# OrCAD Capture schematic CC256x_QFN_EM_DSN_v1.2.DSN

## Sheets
1 Page1 - Board Interafce: size B; title: CC256xQFN-EM; rev: 1.2
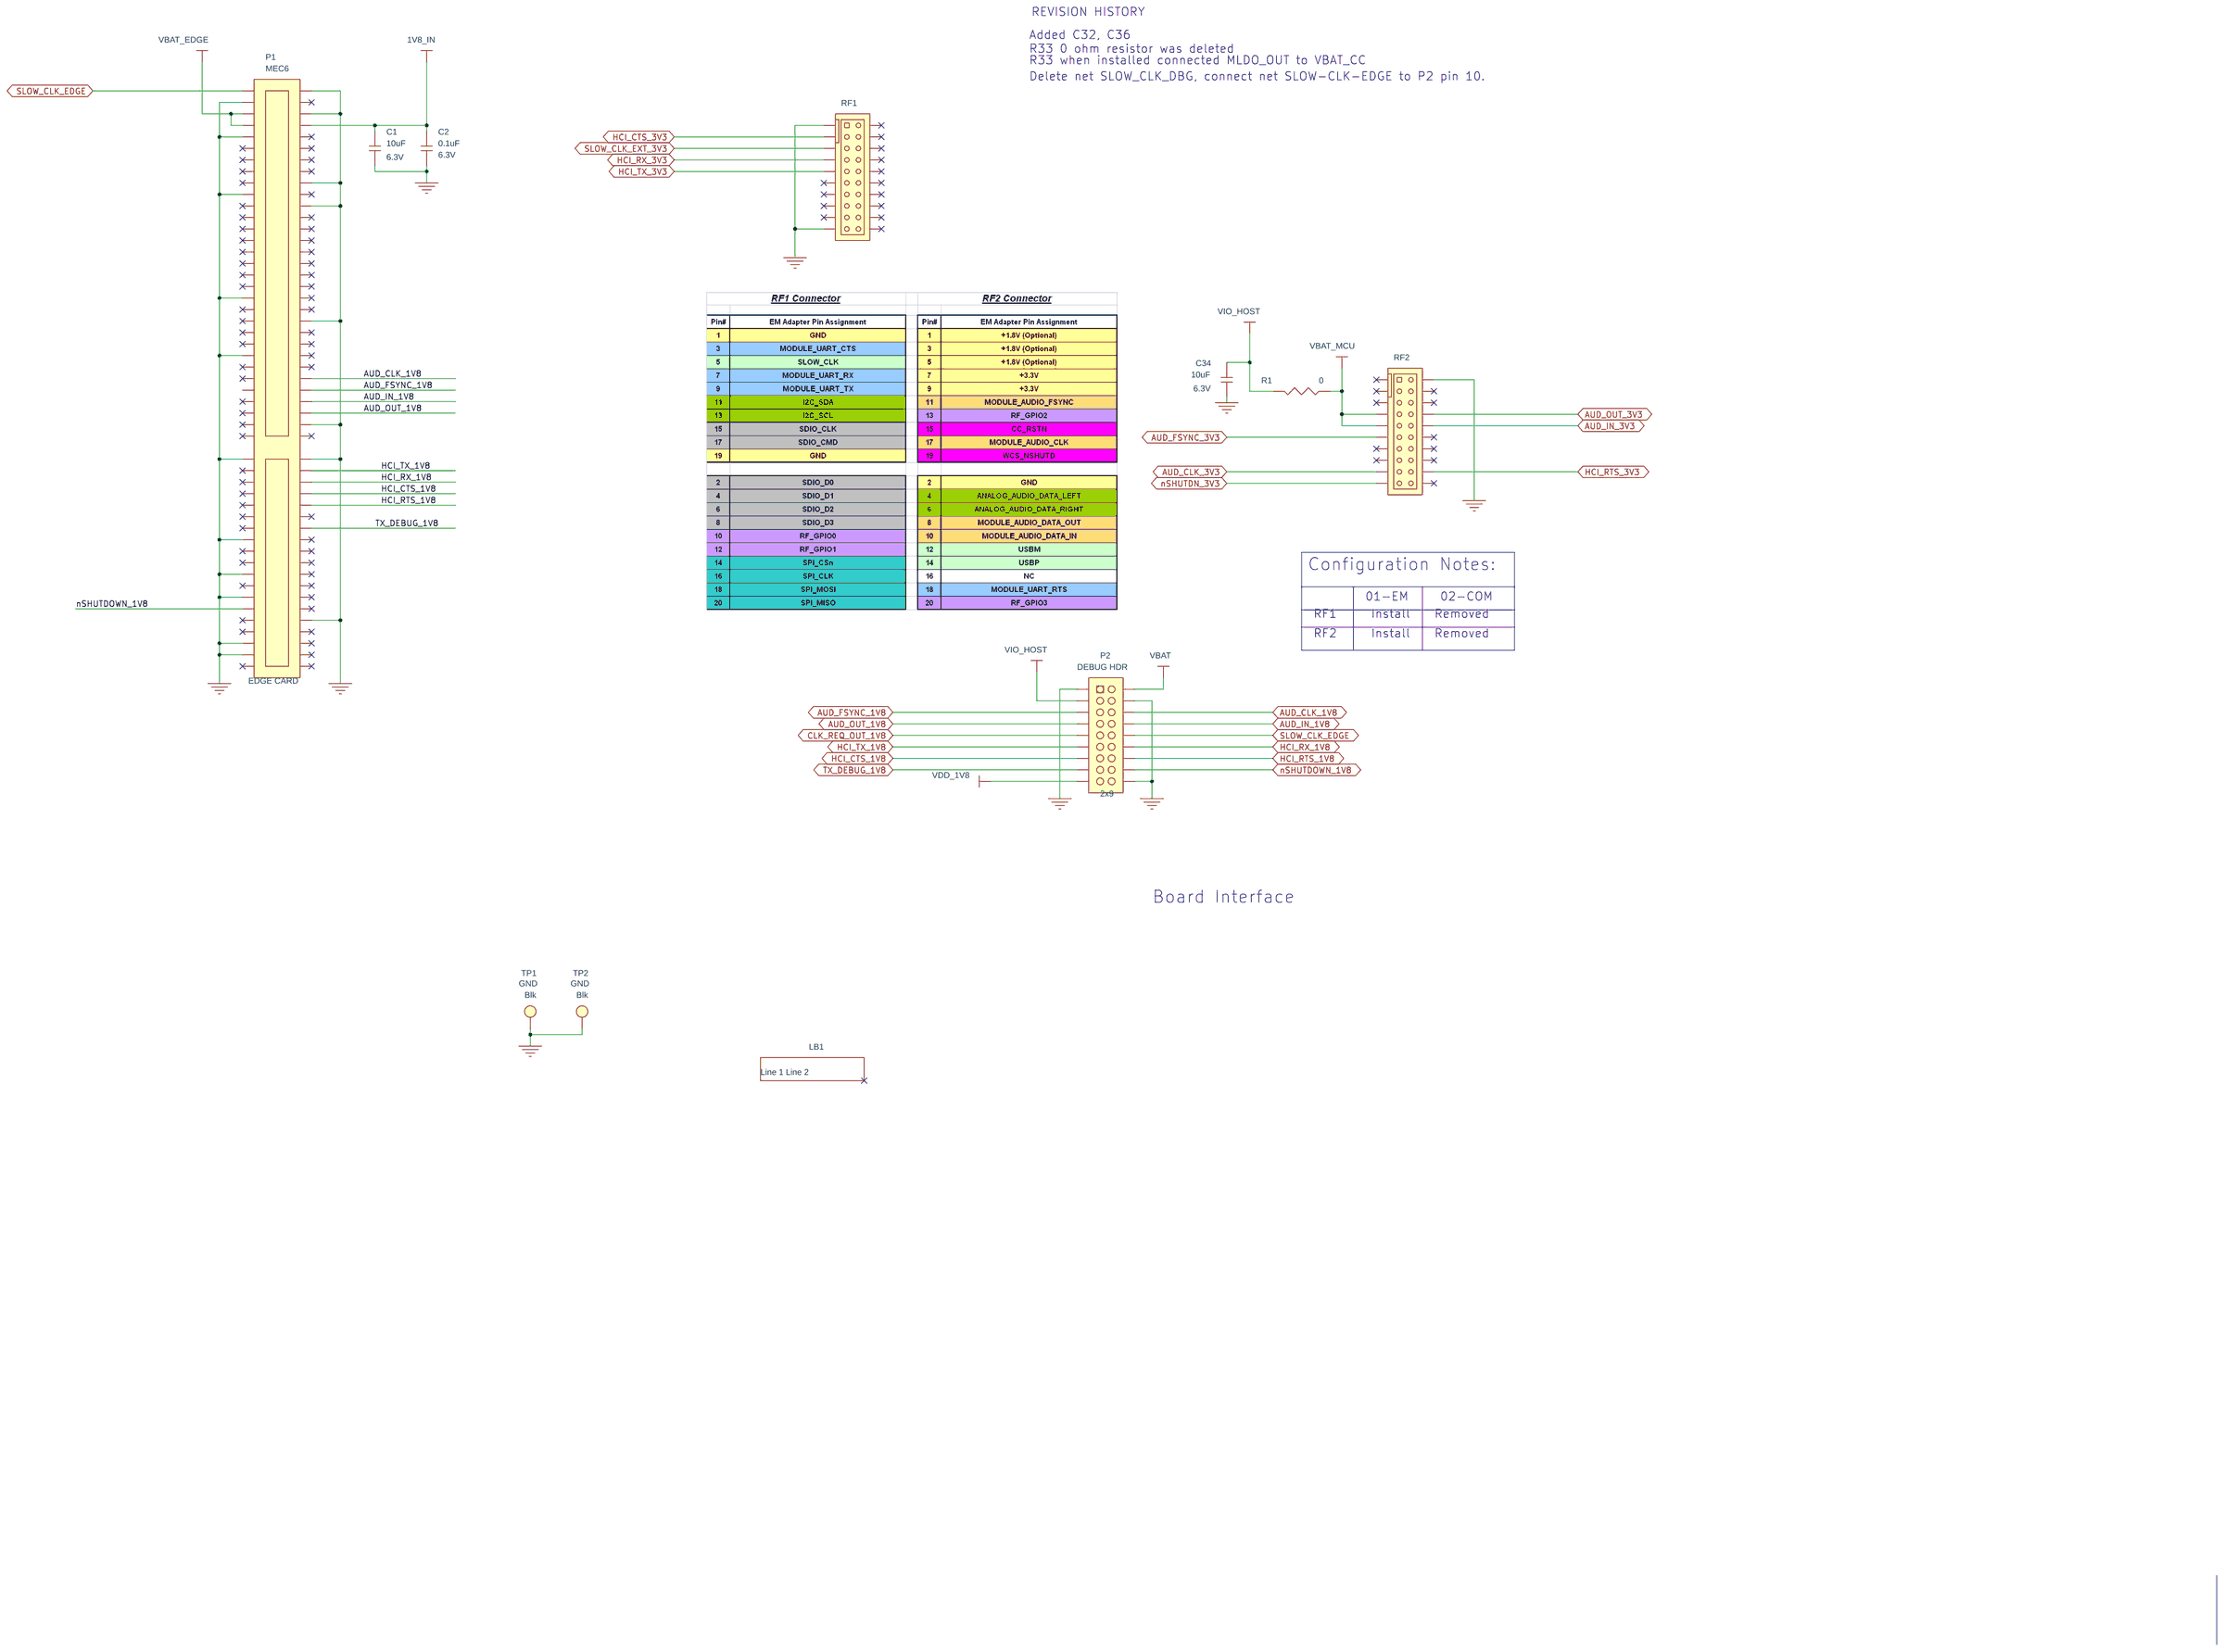
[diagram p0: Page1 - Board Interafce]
2 Page2 - POWER: size B
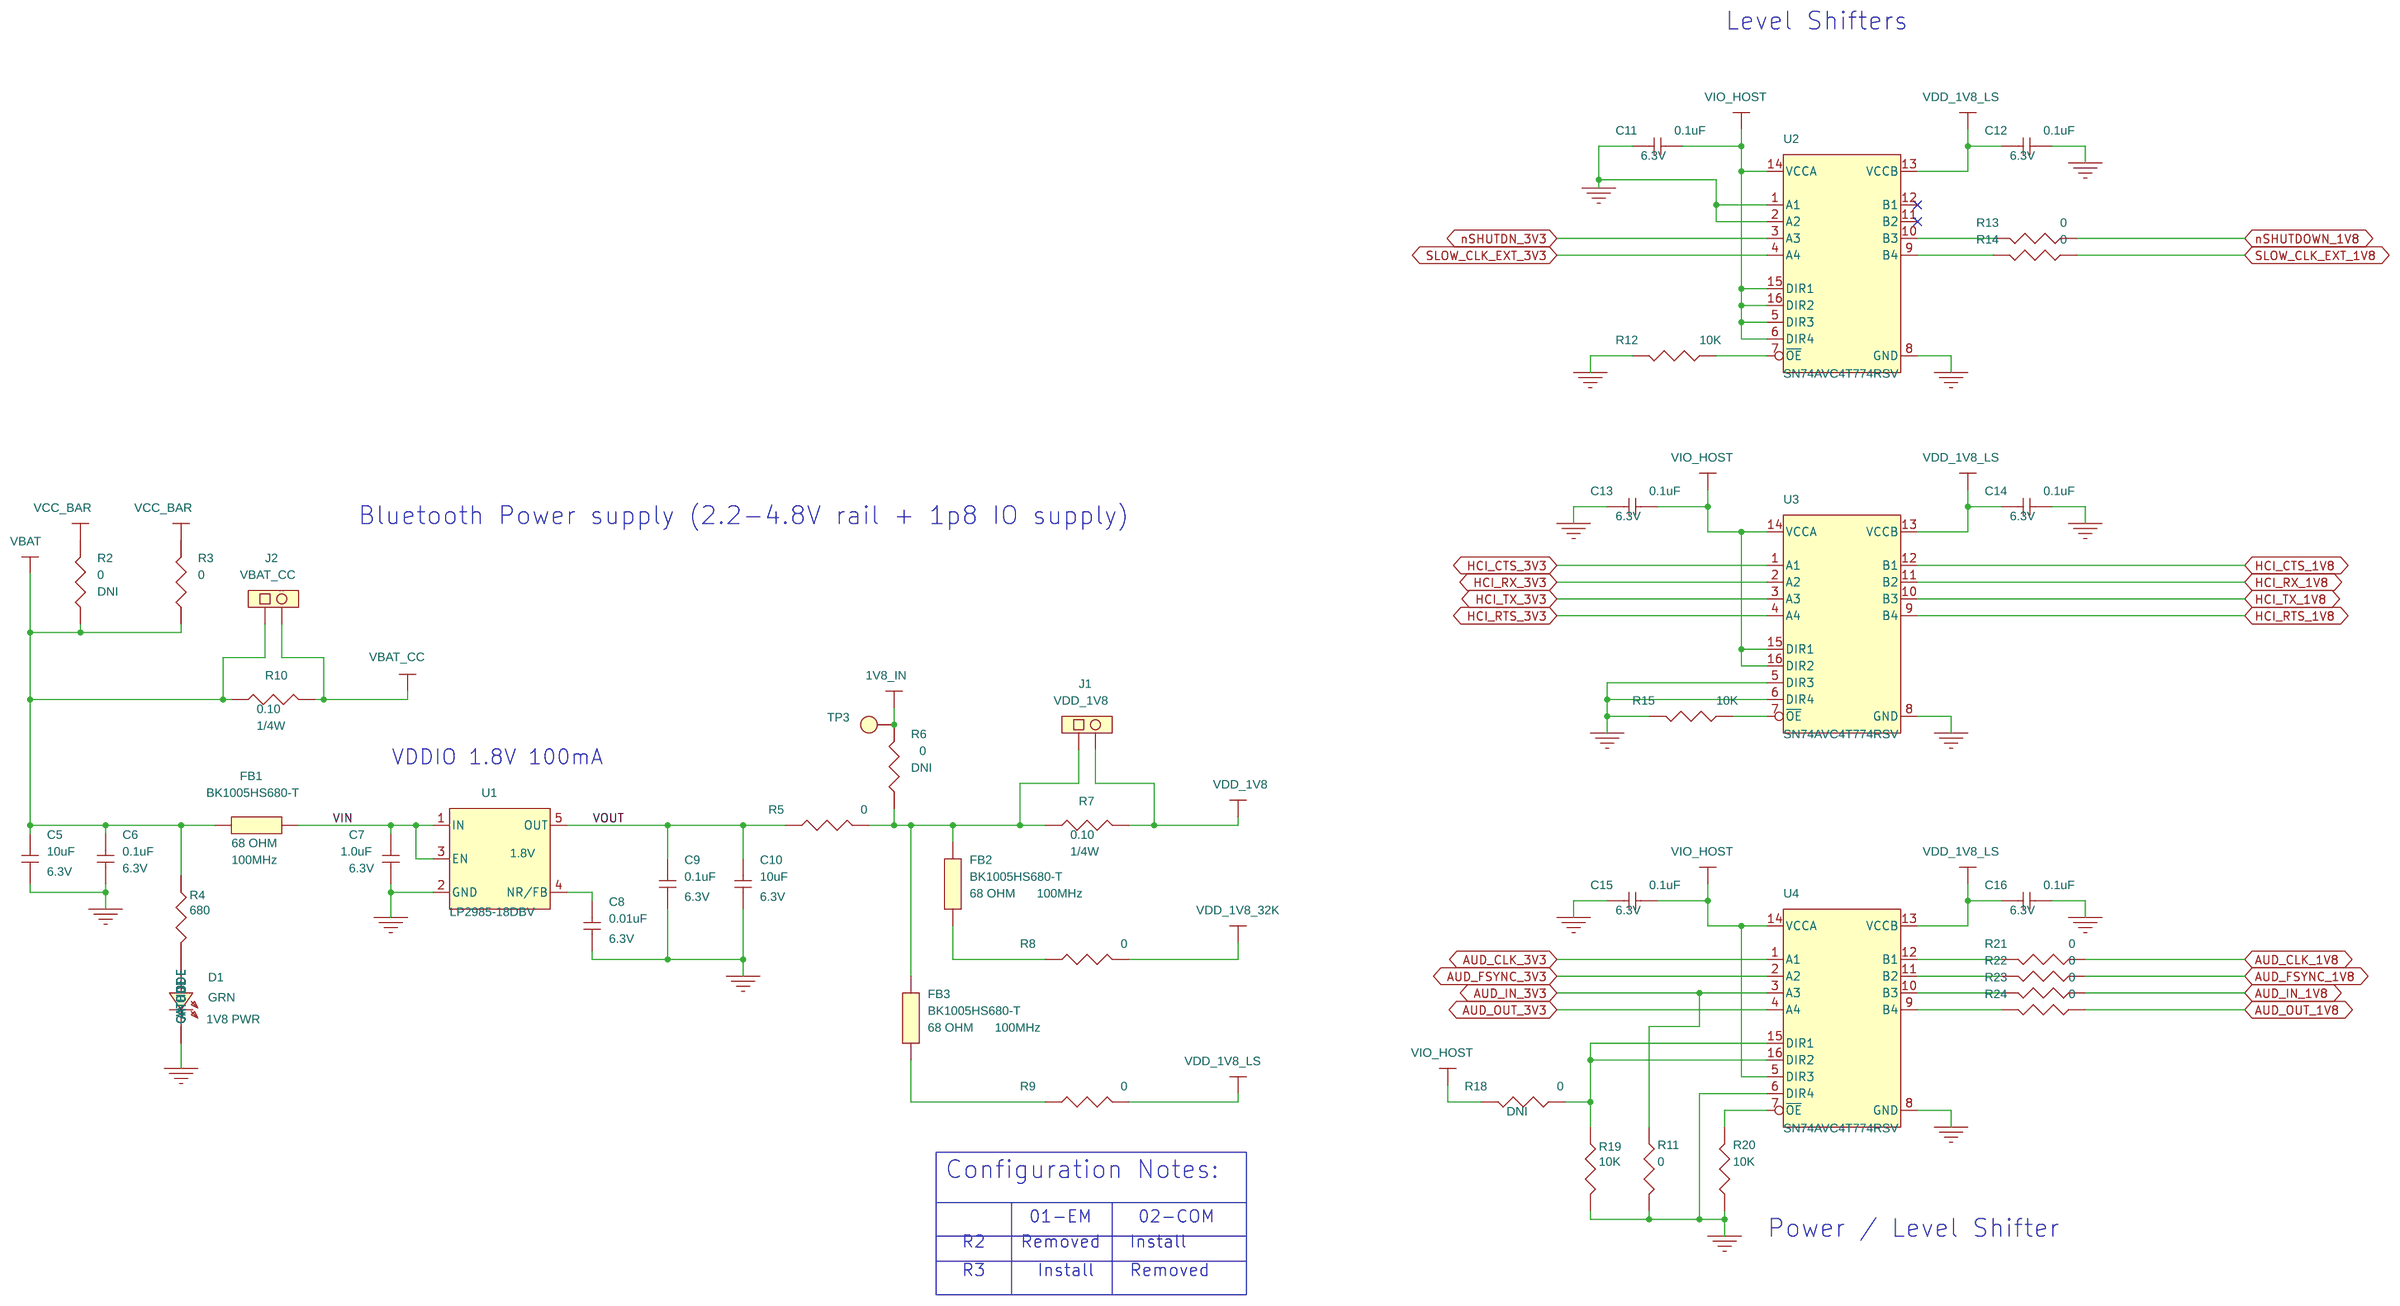
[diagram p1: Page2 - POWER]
3 Page3 - CC256x QFN: size B
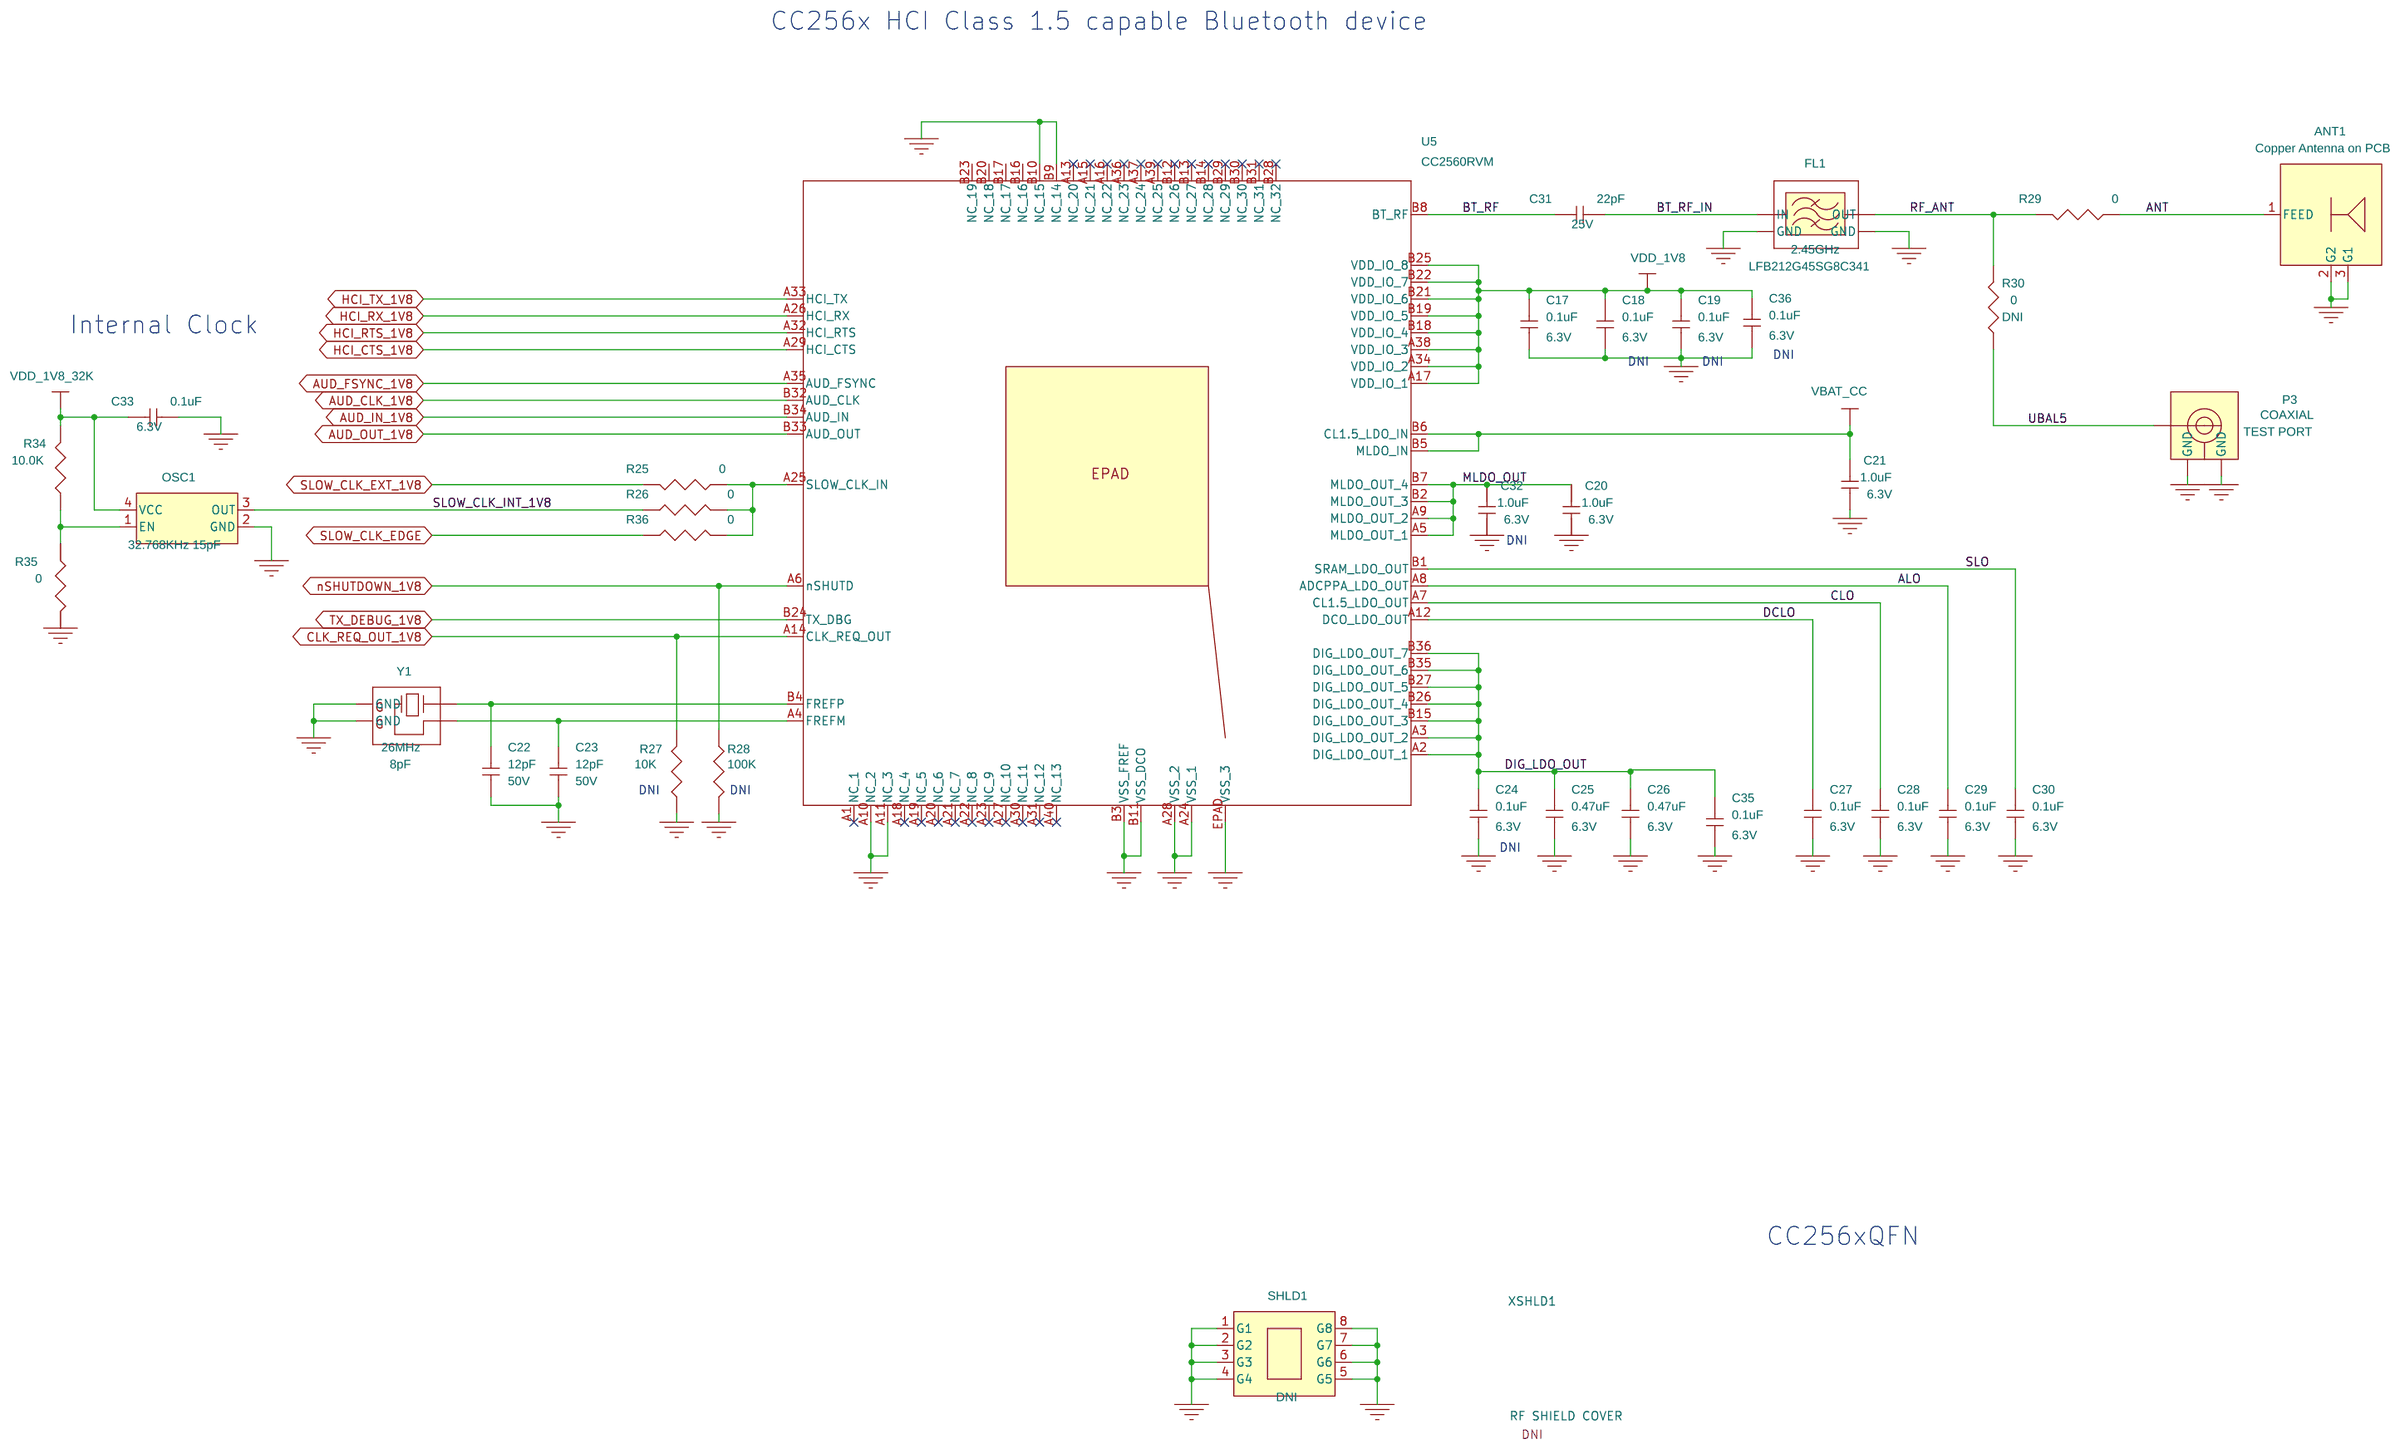
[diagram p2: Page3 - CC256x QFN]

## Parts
sheet Page1 - Board Interafce
C1  10uF  [0603]
C2  0.1uF  [0402]
C34  10uF  [0603]
LB1  Line 1 Line 2  [LABEL_THT-14]
P1  EDGE CARD  [CON_EDGE_50_P635mm]
P2  2x9  [HDR_THVT_2x9_100_M]
R1  0  [0402]
RF1  2x10 SMVT  [CON_SMVT_2x10_50_F_SFM_FLIP_CC]
RF2  2x10 SMVT  [CON_SMVT_2x10_50_F_SFM_FLIP_CC]
TP1  Blk  [TP_THVT_060_RND]
TP2  Blk  [TP_THVT_060_RND]
sheet Page2 - POWER
C5  10uF  [0603]
C6  0.1uF  [0402]
C7  1.0uF  [0402]
C8  0.01uF  [0402]
C9  0.1uF  [0402]
C10  10uF  [0603]
C11  0.1uF  [0402]
C12  0.1uF  [0402]
C13  0.1uF  [0402]
C14  0.1uF  [0402]
C15  0.1uF  [0402]
C16  0.1uF  [0402]
D1  GRN  [LED_0603]
FB1  BK1005HS680-T  [FB_0402]
FB2  BK1005HS680-T  [FB_0402]
FB3  BK1005HS680-T  [FB_0402]
J1  1x2 THVT  [HDR_THVT_1x2_100_M]
J2  1x2 THVT  [HDR_THVT_1x2_100_M]
R2  0  [0402]
R3  0  [0402]
R4  680  [0402]
R5  0  [0402]
R6  0  [0402]
R7  0.10  [0805]
R8  0  [0402]
R9  0  [0402]
R10  0.10  [0805]
R11  0  [0402]
R12  10K  [0402]
R13  0  [0402]
R14  0  [0402]
R15  10K  [0402]
R18  0  [0402]
R19  10K  [0402]
R20  10K  [0402]
R21  0  [0402]
R22  0  [0402]
R23  0  [0402]
R24  0  [0402]
TP3  XX  [TP_VIA_030RND020]
U1  LP2985-18DBV  [SOT23_DBV5]
U2  SN74AVC4T774RSV  [PQFP_RSV16]
U3  SN74AVC4T774RSV  [PQFP_RSV16]
U4  SN74AVC4T774RSV  [PQFP_RSV16]
sheet Page3 - CC256x QFN
ANT1  N/A  [ANT_IIFA_CC2420_32mil_MIR]
C17  0.1uF  [0402]
C18  0.1uF  [0402]
C19  0.1uF  [0402]
C20  1.0uF  [0402]
C21  1.0uF  [0402]
C22  12pF  [0402]
C23  12pF  [0402]
C24  0.1uF  [0402]
C25  0.47uF  [0402]
C26  0.47uF  [0402]
C27  0.1uF  [0402]
C28  0.1uF  [0402]
C29  0.1uF  [0402]
C30  0.1uF  [0402]
C31  22pF  [0201]
C32  1.0uF  [0402]
C33  0.1uF  [0402]
C35  0.1uF  [0402]
C36  0.1uF  [0402]
FL1  2.45GHz  [FIL_4_85x53x41]
OSC1  32.768KHz 15pF  [OSC_4_SM_134X67X40]
P3  COAXIAL  [CON_COAXIAL_UFL-R-SMT]
R25  0  [0402]
R26  0  [0402]
R27  10K  [0402]
R28  100K  [0402]
R29  0  [0402]
R30  0  [0402]
R34  10.0K  [0402]
R35  0  [0402]
R36  0  [0402]
SHLD1  xx  [SH_BMI-S-202_650x650]
U5  CC2560RVM  [PVQFN_RVM_EP134X122]
XSHLD1  RF SHIELD COVER
Y1  26MHz  [XTAL_4_SM_83x67x20]

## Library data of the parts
C1 C5 C10 C34 = CAP_NP: Link2Local Datasheet: C:\PCB_LIBRARY\CADENCE\DATASHEETS\mlcc01_e.pdf; Link2MFG Datasheet: http://www.yuden.co.jp/ut/product/pdf/mlcc01_e.pdf; Manufacturer: Taiyo Yuden; Manufacturer Part Number: JMK107BJ106MA-T; Part Description: CAP CER 10UF 6.3V X5R 0603; TEMP °C: -55 to 85; Voltage: 6.3V
C2 C6 C9 C11-C19 C24 C27-C30 C33 C35 C36 = CAP_NP: ALT_SYMBOLS: 0402_SMALL; Link2MFG Datasheet: http://www.kemet.com/kemet/web/homepage/kechome.nsf/vapubfiles/F3102_X7R.pdf/$file/F3102_X7R.pdf; Manufacturer: Kemet; Manufacturer Part Number: C0402C104K9RACTU; Part Description: CAP CER 0.1UF 6.3V 10% X7R 0402; TEMP °C: -55 to 125; Voltage: 6.3V
LB1 = LABEL_BOARD: Link2MFG Datasheet: http://www.bradyid.com/bradyid/pdpv/THT-14-423-10.html; Manufacturer: Brady; Manufacturer Part Number: THT-14-423-10; Note: See Assembly drawing for location; Part Description: 650x200 Label UL,CSA,AGA approved
P1 = CON_EDGE_2x50_25_MEC6: Link2MFG Datasheet: http://www.samtec.com/documents/webfiles/cpdf/MEC6-1XX-XX-X-DV-XX-FOOTPRINT.pdf; Part Description: EDGE CARD, MATES WITH SAMTEC MEC6-150 SERIES SOCKET, 0.025" PITCH; TI_SILKTEXT: MEC6
P2 = HEADER_2x9_100_430L: Manufacturer: Samtec; Manufacturer Part Number: HMTSW-109-07-G-D-230; Part Description: HEADER_2x9_100_THVT_M_430L; TI_SILKTEXT: DEBUG HDR
R1 R3 R5 R8 R9 R11 R13 R14 R21-R24 R35 = RESISTOR: Link2Local Datasheet: C:\PCB_LIBRARY\CADENCE\DATASHEETS\AOA0000PE2.pdf; Link2MFG Datasheet: http://industrial.panasonic.com/www-cgi/jvcr13pz.cgi?E+PZ+3+AOA0001+ERJ3GEY0R00V+7+WW; Manufacturer: Panasonic - ECG; Manufacturer Part Number: ERJ-2GE0R00X; Part Description: RES 0.0 OHM 1/10W 0402 SMD; TEMP °C: -100/+600ppm/°C; Watt: 1/10W
RF1 = CON_2x10_FLIP_CC: Link2Local Datasheet: C:\PCB_LIBRARY\CADENCE\DATASHEETS\SFM_Series; Link2MFG Datasheet: http://www.samtec.com/documents/webfiles/pdf/SFM_SM.PDF; Manufacturer: Samtec; Note: SEE ASSEMBLY FOR PIN 1 LOCATION; TEMP °C: -55 to 125
RF2 = CON_2x10_FLIP_CC: Link2Local Datasheet: C:\PCB_LIBRARY\CADENCE\DATASHEETS\SFM_Series; Link2MFG Datasheet: http://www.samtec.com/documents/webfiles/pdf/SFM_SM.PDF; Manufacturer: Samtec; Note: SEE ASSEMBLY FOR PIN 1 LOCATION; TEMP °C: -55 to 125; TI_SILKTEXT: RF1
TP1 TP2 = TESTPOINT: Link2Local Datasheet: C:\PCB_LIBRARY\CADENCE\DATASHEETS\TP-105.pdf; Link2MFG Datasheet: http://www.componentscorp.com/pdf/TP-105.pdf; Manufacturer: Components Corporation; Manufacturer Part Number: TP-105-01-00; Part Description: TEST POINT .025" SQR POST HDR BLACK; TI_SILKTEXT: GND
C7 C20 C21 C32 = CAP_NP: ALT_SYMBOLS: 0402_SMALL; Link2MFG Datasheet: http://search.digikey.com/scripts/DkSearch/dksus.dll?Detail&name=587-2594-2-ND; Manufacturer: Taiyo Yuden; Manufacturer Part Number: JMK105BJ105KV-F; Part Description: CAP CER 1.0UF 6.3V X5R 10% 0402; TEMP °C: -55 to 85; Voltage: 6.3V
C8 = CAP_NP: ALT_SYMBOLS: 0402_SMALL; Link2MFG Datasheet: http://www.tdk.com/pdf/general_B11.pdf; Manufacturer: TDK; Manufacturer Part Number: C0402X5R0J103K; Part Description: CAP CER 0.01uF 6.3V 10% X5R 0402; TEMP °C: -40 to 85; Voltage: 6.3V
D1 = LED_2P: Link2Local Datasheet: C:\PCB_LIBRARY\CADENCE\DATASHEETS\LNJ208R8ARA_BEK.pdf; Link2MFG Datasheet: http://www.semicon.panasonic.co.jp/ds4/LNJ208R8ARA_BEK.pdf; Manufacturer: OSRAM Opto Semiconductors Inc; Manufacturer Part Number: LG L29K-G2J1-24-Z; Part Description: LED GREEN HI BRT SS TYPE LO CUR SM; TI_SILKTEXT: 1V8 PWR; Voltage: 1.72V
FB1-FB3 = FERRITE_BEAD: Manufacturer: Taiyo Yuden; Part Description: FERRITE BEAD 68 OHM 0402; Voltage: 68 OHM; Watt: 100MHz
J1 = Header_1x2: Link2Local Datasheet: C:\PCB_LIBRARY\CADENCE\DATASHEETS\HMTSW_SERIES; Link2MFG Datasheet: http://www.samtec.com/ProductInformation/TechnicalSpecifications/Overview.aspx?series=HMTSW; Manufacturer: Samtec; Manufacturer Part Number: HMTSW-102-07-G-S-230; Part Description: MODIFIED .025" SQ POST HEADERS,1X2,PITCH=.100",POST=230"; TEMP °C: -55 TO 125; TI_SILKTEXT: VDD_1V8
J2 = Header_1x2: Link2Local Datasheet: C:\PCB_LIBRARY\CADENCE\DATASHEETS\HMTSW_SERIES; Link2MFG Datasheet: http://www.samtec.com/ProductInformation/TechnicalSpecifications/Overview.aspx?series=HMTSW; Manufacturer: Samtec; Manufacturer Part Number: HMTSW-102-07-G-S-230; Part Description: MODIFIED .025" SQ POST HEADERS,1X2,PITCH=.100",POST=230"; TEMP °C: -55 TO 125; TI_SILKTEXT: VBAT_CC
R2 R6 = RESISTOR: Link2Local Datasheet: C:\PCB_LIBRARY\CADENCE\DATASHEETS\AOA0000PE2.pdf; Link2MFG Datasheet: http://industrial.panasonic.com/www-cgi/jvcr13pz.cgi?E+PZ+3+AOA0001+ERJ3GEY0R00V+7+WW; Manufacturer: Panasonic - ECG; Manufacturer Part Number: ERJ-2GE0R00X; Note: DNI; Part Description: RES 0.0 OHM 1/10W 0402 SMD; TEMP °C: -100/+600ppm/°C; Watt: 1/10W
R4 = RESISTOR: ALT_SYMBOLS: 0402_SMALL; Link2MFG Datasheet: http://search.digikey.com/scripts/DkSearch/dksus.dll?Detail&name=P680JTR-ND; Manufacturer: Panasonic - ECG; Manufacturer Part Number: ERJ-2GEJ681X; Part Description: RES Thick Film 680 OHM 1/10W 5% 0402; TEMP °C: ±200ppm/°C; Watt: 1/10W
R7 R10 = RESISTOR: Link2Local Datasheet: C:\PCB_LIBRARY\CADENCE\DATASHEETS\PT0805 High Power Series.pdf; Link2MFG Datasheet: http://media.digikey.com/pdf/Data%20Sheets/Yageo%20PDFs/PT0805%20High%20Power%20Series.pdf; Manufacturer: Rohm Semiconductor; Manufacturer Part Number: MCR10EZHFLR100; Part Description: RES 0.10 OHM 0.25W 1% 0805 SMD; TEMP °C: ±100ppm/°C; Watt: 1/4W
R12 R15 R19 R20 R27 = RESISTOR: ALT_SYMBOLS: 0402_SMALL; Link2Local Datasheet: C:\PCB_LIBRARY\CADENCE\DATASHEETS\AOA0000PE3.pdf; Link2MFG Datasheet: http://industrial.panasonic.com/www-data/pdf/AOA0000/AOA0000PE2.pdf; Manufacturer: Panasonic - ECG; Manufacturer Part Number: ERJ-2GEJ103X; Part Description: RES 10K OHM 1/10W 5% 0402 SMD; TEMP °C: ±200ppm/°C; Watt: 1/10W
R18 R26 R30 R36 = RESISTOR: ALT_SYMBOLS: 0402_SMALL; Link2MFG Datasheet: http://search.digikey.com/scripts/DkSearch/dksus.dll?Detail&name=P0.0JTR-ND; Manufacturer: Panasonic - ECG; Manufacturer Part Number: ERJ-2GE0R00X; Note: DNI; Part Description: RES 0.0 OHM 1/10W 0402 SMD; TEMP °C: -100/+600ppm/°C; Watt: 1/10W
TP3 = TESTPOINT: Note: NO PART.  TEST PAD ONLY
U1 = TPS731xx_DBV5: Link2MFG Datasheet: http://www.ti.com/lit/ds/symlink/lp2985-18.pdf; Part Description: IC REG LDO 1.8V 0.15A SOT23-5; TEMP °C: -40 to 125; Voltage: 1.8V
U2-U4 = SN74AVC4T774_RSV16: Link2Local Datasheet: C:\PCB_LIBRARY\CADENCE\DATASHEETS\sn74avc4t245.pdf; Link2MFG Datasheet: http://www.ti.com/lit/ds/symlink/sn74avc4t774.pdf; Manufacturer: Texas Intruments; Part Description: IC BUS TRANSCVR 4BIT WITH 1.2-3.6V 16-UQFN; TEMP °C: -40 to 85
ANT1 = ANT_IIFA_CC2420_32mil_MIR: NOTE: Copper Antenna on PCB
C22 C23 = CAP_NP: ALT_SYMBOLS: 0402_SMALL; Link2Local Datasheet: C:\PCB_LIBRARY\CADENCE\DATASHEETS\GRM1555C1H100JZ01.pdf; Link2MFG Datasheet: http://search.digikey.com/scripts/DkSearch/dksus.dll?Detail&name=490-1278-2-ND; Manufacturer: Murata Electronics; Manufacturer Part Number: GRM1555C1H100JZ01D; Part Description: CAP CER 10PF 50V 5% NP0 0402; TEMP °C: -55 to 125; Voltage: 50V
C25 C26 = CAP_NP: ALT_SYMBOLS: 0402_SMALL; Link2Local Datasheet: C:\PCB_LIBRARY\CADENCE\DATASHEETS\dlmk_e.pdf; Link2MFG Datasheet: http://www.yuden.co.jp/ut/product/pdf/dlmk_e.pdf; Manufacturer: Taiyo Yuden; Manufacturer Part Number: JMK105BJ474KV-F; Part Description: CAP CER .47UF 6.3V X5R ±10% 0402; TEMP °C: -55 to 85; Voltage: 6.3V
C31 = CAP_NP: ALT_SYMBOLS: 0201_small; Link2MFG Datasheet: http://search.digikey.com/us/en/products/GRM0335C1E1R8CD01D/490-1244-2-ND/587245; Manufacturer: Murata Electronics North America; Manufacturer Part Number: GRM0335C1E220JD01D; Part Description: CAP CER 22PF 25V 5% NP0 0201; TEMP °C: -55 to 125; Voltage: 25V
FL1 = FILTER_4PIN_GND: Link2Local Datasheet: C:\PCB_LIBRARY\CADENCE\DATASHEETS\Search Engine  Murata Manufacturing; Link2MFG Datasheet: http://search.murata.co.jp/Ceramy/CatalogAction.do?sHinnm=?%C2%A0&sNHinnm=LFB212G45SG8A127&sNhin_key=LFB212G45SG8A127&sLang=en; Manufacturer: Murata Electronics; Manufacturer Part Number: LFB212G45SG8C341; Note: PLACE BROWN MARKING UP; Part Description: FILTER CER BAND PASS 2.45GHZ SMD
OSC1 = OSC_4_SM_3-OUT: Link2MFG Datasheet: http://www.abracon.com/Oscillators/ASH7K.pdf; Manufacturer: Abracon Corporation; Manufacturer Part Number: ASH7K-32.768KHZ-T; Part Description: OSC 32.768 KHZ 15pF 1.5V 3.3V SMD; TEMP °C: -40 to 85; Voltage: 1.8 to 3.6V
P3 = CON_COAXIAL_UFL-R-SMT: Part Description: RECEPTACLE_CON_COAXIAL_UFL-R-SMT; TI_SILKTEXT: TEST PORT
R25 R29 = RESISTOR: ALT_SYMBOLS: 0402_SMALL; Link2MFG Datasheet: http://search.digikey.com/scripts/DkSearch/dksus.dll?Detail&name=P0.0JTR-ND; Manufacturer: Panasonic - ECG; Manufacturer Part Number: ERJ-2GE0R00X; Part Description: RES 0.0 OHM 1/10W 0402 SMD; TEMP °C: -100/+600ppm/°C; Watt: 1/10W
R28 = RESISTOR: ALT_SYMBOLS: 0402_SMALL; Link2Local Datasheet: C:\PCB_LIBRARY\CADENCE\DATASHEETS\AOA0000PE3.pdf; Link2MFG Datasheet: http://industrial.panasonic.com/www-data/pdf/AOA0000/AOA0000PE2.pdf; Manufacturer: Panasonic - ECG; Manufacturer Part Number: ERJ-2GEJ104X; Part Description: RES 100K OHM 1/10W 5% 0402 SMD; TEMP °C: ±200ppm/°C; Watt: 1/10W
R34 = RESISTOR: ALT_SYMBOLS: 0402_SMALL; Link2Local Datasheet: C:\PCB_LIBRARY\CADENCE\DATASHEETS\AOA0000PE3.pdf; Link2MFG Datasheet: http://industrial.panasonic.com/www-data/pdf/AOA0000/AOA0000PE3.pdf; Manufacturer: Panasonic - ECG; Manufacturer Part Number: ERJ-2RKF1002X; Part Description: RES 10.0K OHM 1/10W 1% 0402 SMD; TEMP °C: ±100ppm/°C; Watt: 1/10W
SHLD1 = RF_SHIELD_8P: Manufacturer: Laird Technologies EMI; Manufacturer Part Number: BMI-S-202-F; Note: DNI; Part Description: BOARD SHIELD .65X.65" FRAME
U5 = BL6450Q_RVM: Link2Local Datasheet: C:\PCB_LIBRARY\CADENCE\DATASHEETS\SWRS115A_BL6450Q_ProductPreview.pdf; Link2MFG Datasheet: DRAFT ONLY; Manufacturer: Texas Instruments; Manufacturer Part Number: CC256xRVM; Part Description: Bluetooth BR/EDR/LE and ANT Single-Chip Solution
XSHLD1 = RF_SHIELD_COVER: Link2Local Datasheet: C:\PCB_LIBRARY\CADENCE\DATASHEETS\EMI_Board_Level_Shields_and_Contacts.pdf; Link2MFG Datasheet: http://search.digikey.com/scripts/DkSearch/dksus.dll?Detail&name=903-1013-ND; Manufacturer: Laird Technologies EMI; Manufacturer Part Number: BMI-S-202-C; Note: DNI; Part Description: BOARD SHIELD .650X.650" COVER
Y1 = XTAL_4P_GND: Link2Local Datasheet: C:\PCB_LIBRARY\CADENCE\DATASHEETS\FA-128_E107.pdf; Link2MFG Datasheet: http://ndap3-net.ebz.epson.co.jp/w/www/PDFS/epdoc_qd.nsf/85a4e2c523a1f89349257068002f9e30/255cb2884010a1f9492571f0004c7d72/$FILE/FA-128_E107.pdf; Load Cap: 8pF; Manufacturer: AVX Corporation; Manufacturer Part Number: CX2016DB26000D0FLJZ1; Part Description: CRYSTAL,26MHz,8pF,SMD,FA-128 SERIES 4P; TEMP °C: -20 to 70

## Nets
1V8_IN: C1.1 C2.1 P1.8 R6.2 TP3.1
GND: ANT1.2(G2) ANT1.3(G1) C1.2 C2.2 C5.2 C6.2 C7.2 C8.2 C9.2 C10.2 C11.1 C12.2 C13.1 C14.2 C15.1 C16.2 C17.2 C18.2 C19.2 C20.2 C21.2 C22.1 C23.1 C24.2 C25.2 C26.2 C27.2 C28.2 C29.2 C30.2 C32.2 C33.2 C34.2 C35.2 C36.2 D1.2(CATHODE) FL1.1(GND) FL1.3(GND) OSC1.2(GND) P1.2 P1.3 P1.6 P1.9 P1.18 P1.19 P1.22 P1.37 P1.42 P1.47 P1.60 P1.63 P1.64 P1.77 P1.83 P1.87 P1.92 P1.95 P1.97 P2.1 P2.4 P2.18 P3.1(GND) P3.3(GND) R11.2 R12.2 R15.2 R19.2 R20.1 R27.2 R28.2 R35.1 RF1.1 RF1.19 RF2.2 SHLD1.1(G1) SHLD1.2(G2) SHLD1.3(G3) SHLD1.4(G4) SHLD1.5(G5) SHLD1.6(G6) SHLD1.7(G7) SHLD1.8(G8) TP1.1 TP2.1 U1.2(GND) U2.1(A1) U2.2(A2) U2.8(GND) U3.5(DIR3) U3.6(DIR4) U3.8(GND) U4.6(DIR4) U4.8(GND) U5.A10(NC_2) U5.A11(NC_3) U5.A24(VSS_1) U5.A28(VSS_2) U5.B3(VSS_FREF) U5.B9(NC_14) U5.B10(NC_15) U5.B11(VSS_DCO) U5.EPAD(VSS_3) Y1.2(GND) Y1.4(GND)
VBAT: C5.1 C6.1 FB1.1 J2.1 P2.2 R2.1 R3.1 R4.1 R10.1
VBAT_CC: C21.1 J2.2 R10.2 U5.B5(MLDO_IN) U5.B6(CL1.5_LDO_IN)
VBAT_EDGE: P1.5 P1.7 R2.2
VBAT_MCU: R1.1 R3.2 RF2.7 RF2.9
VDD_1V8: C17.1 C18.1 C19.1 C36.1 J1.2 P2.17 R7.2 U5.A17(VDD_IO_1) U5.A34(VDD_IO_2) U5.A38(VDD_IO_3) U5.B18(VDD_IO_4) U5.B19(VDD_IO_5) U5.B21(VDD_IO_6) U5.B22(VDD_IO_7) U5.B25(VDD_IO_8)
VDD_1V8_32K: C33.1 OSC1.4(VCC) R8.2 R34.1
VDD_1V8_LS: C12.1 C14.1 C16.1 R9.2 U2.13(VCCB) U3.13(VCCB) U4.13(VCCB)
VIN: C7.1 FB1.2 U1.1(IN) U1.3(EN)
ALO: C29.1 U5.A8(ADCPPA_LDO_OUT)
ANT: ANT1.1(FEED) R29.1
AUD_CLK_1V8: P1.52 P2.6 R21.1 U5.B32(AUD_CLK)
AUD_CLK_3V3: RF2.17 U4.1(A1)
AUD_FSYNC_1V8: P1.54 P2.5 R22.1 U5.A35(AUD_FSYNC)
AUD_FSYNC_3V3: RF2.11 U4.2(A2)
AUD_IN_1V8: P1.56 P2.8 R23.1 U5.B34(AUD_IN)
AUD_IN_3V3: R11.1 RF2.10 U4.3(A3)
AUD_OUT_1V8: P1.58 P2.7 R24.1 U5.B33(AUD_OUT)
AUD_OUT_3V3: RF2.8 U4.4(A4)
BT_RF: C31.1 U5.B8(BT_RF)
BT_RF_IN: C31.2 FL1.4(IN)
CLK_REQ_OUT_1V8: P2.9 R27.1 U5.A14(CLK_REQ_OUT)
CLO: C28.1 U5.A7(CL1.5_LDO_OUT)
DCLO: C27.1 U5.A12(DCO_LDO_OUT)
DIG_LDO_OUT: C24.1 C25.1 C26.1 C35.1 U5.A2(DIG_LDO_OUT_1) U5.A3(DIG_LDO_OUT_2) U5.B15(DIG_LDO_OUT_3) U5.B26(DIG_LDO_OUT_4) U5.B27(DIG_LDO_OUT_5) U5.B35(DIG_LDO_OUT_6) U5.B36(DIG_LDO_OUT_7)
HCI_CTS_1V8: P1.70 P2.13 U3.12(B1) U5.A29(HCI_CTS)
HCI_CTS_3V3: RF1.3 U3.1(A1)
HCI_RTS_1V8: P1.72 P2.14 U3.9(B4) U5.A32(HCI_RTS)
HCI_RTS_3V3: RF2.18 U3.4(A4)
HCI_RX_1V8: P1.68 P2.12 U3.11(B2) U5.A26(HCI_RX)
HCI_RX_3V3: RF1.7 U3.2(A2)
HCI_TX_1V8: P1.66 P2.11 U3.10(B3) U5.A33(HCI_TX)
HCI_TX_3V3: RF1.9 U3.3(A3)
MLDO_OUT: C20.1 C32.1 U5.A5(MLDO_OUT_1) U5.A9(MLDO_OUT_2) U5.B2(MLDO_OUT_3) U5.B7(MLDO_OUT_4)
nSHUTDN_3V3: RF2.19 U2.3(A3)
nSHUTDOWN_1V8: P1.89 P2.16 R13.1 R28.1 U5.A6(nSHUTD)
RF_ANT: FL1.2(OUT) R29.2 R30.2
SLO: C30.1 U5.B1(SRAM_LDO_OUT)
SLOW_CLK_EDGE: P1.1 P2.10 R36.1
SLOW_CLK_EXT_1V8: R14.1 R25.2
SLOW_CLK_EXT_3V3: RF1.5 U2.4(A4)
SLOW_CLK_INT_1V8: OSC1.3(OUT) R26.1
TX_DEBUG_1V8: P1.76 P2.15 U5.B24(TX_DBG)
UBAL5: P3.2 R30.1
VIO_HOST: C11.2 C13.2 C15.2 C34.1 P2.3 R1.2 R18.2 U2.5(DIR3) U2.6(DIR4) U2.14(VCCA) U2.15(DIR1) U2.16(DIR2) U3.14(VCCA) U3.15(DIR1) U3.16(DIR2) U4.5(DIR3) U4.14(VCCA)
VOUT: C9.1 C10.1 R5.1 U1.5(OUT)
N29501739: C8.1 U1.4(NR/FB)
N29523209: FB2.1 FB3.1 J1.1 R5.2 R6.1 R7.1
N29523238: FB2.2 R8.1
N29550712: FB3.2 R9.1
N29596482: C22.2 U5.B4(FREFP) Y1.1
N29596500: C23.2 U5.A4(FREFM) Y1.3
N29616633: R20.2 U4.7(~{OE})
N29628438: R12.1 U2.7(~{OE})
N29630665: R15.1 U3.7(~{OE})
N29632228: R18.1 R19.1 U4.15(DIR1) U4.16(DIR2)
N29659196: R25.1 R26.2 R36.2 U5.A25(SLOW_CLK_IN)
N29662683: R13.2 U2.10(B3)
N29662686: R14.2 U2.9(B4)
N29662812: R21.2 U4.12(B1)
N29662815: R22.2 U4.11(B2)
N29662818: R23.2 U4.10(B3)
N29662821: R24.2 U4.9(B4)
N29665006: OSC1.1(EN) R34.2 R35.2
N29686902: D1.1(ANODE) R4.2

Not connected (* = marked no-connect by the designer): LB1 1*; P1 4* 10* 11* 12* 13* 14* 15* 16* 17* 20* 21* 23* 24* 25* 26* 27* 28* 29* 30* 31* 32* 33* 34* 35* 36* 38* 39* 40* 41* 43* 44* 45* 46* 48* 49* 50* 51* 53 55* 57* 59* 61* 62* 65* 67* 69* 71* 73* 74* 75* 78* 79* 80* 81* 82* 84* 85* 86* 88* 90* 91* 93* 94* 96* 98* 99* 100*; RF1 2* 4* 6* 8* 10* 11* 12* 13* 14* 15* 16* 17* 18* 20*; RF2 1* 3* 4* 5* 6* 12* 13* 14* 15* 16* 20*; U2 11(B2)* 12(B1)*; U5 A1(NC_1)* A13(NC_20)* A15(NC_21)* A16(NC_22)* A18(NC_4)* A19(NC_5)* A20(NC_6)* A21(NC_7)* A22(NC_8)* A23(NC_9)* A27(NC_10)* A30(NC_11)* A31(NC_12)* A36(NC_23)* A37(NC_24)* A39(NC_25)* A40(NC_13)* B12(NC_26)* B13(NC_27)* B14(NC_28)* B16(NC_16) B17(NC_17) B20(NC_18) B23(NC_19) B28(NC_32)* B29(NC_29)* B30(NC_30)* B31(NC_31)*

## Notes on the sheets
sheet 1
- REVISION HISTORY
- Added C32, C36
- R33 0 ohm resistor was deleted
- R33 when installed connected MLDO_OUT to VBAT_CC
- Delete net SLOW_CLK_DBG, connect net SLOW-CLK-EDGE to P2 pin 10.
- Configuration Notes:
- 01-EM
- 02-COM
- RF1
- Install
- Removed
- RF2
- Install
- Removed
- Board Interface
sheet 2
- Level Shifters
- Bluetooth Power supply (2.2-4.8V rail + 1p8 IO supply)
- VDDIO 1.8V 100mA
- Configuration Notes:
- 01-EM
- 02-COM
- Power / Level Shifter
- R2
- Removed
- Install
- R3
- Install
- Removed
sheet 3
- CC256x HCI Class 1.5 capable Bluetooth device
- Internal Clock
- DNI
- DNI
- DNI
- DNI
- DNI
- DNI
- DNI
- CC256xQFN
